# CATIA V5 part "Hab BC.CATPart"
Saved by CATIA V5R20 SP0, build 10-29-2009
Part number: Hab BC
Bounding box of the stored display mesh (mm): x -10 to 0, y -419.304 to 209.7, z -16.563 to 441.04
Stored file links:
  D:\Dropbox\IAO_2012\IAO_2012_766_vlaroche\vlaroche\vlaroche\IAO\A rendre\Hab BC.CATPart
  D:\Catia\IAO\A rendre\Assemblage.CATProduct
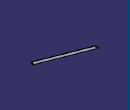
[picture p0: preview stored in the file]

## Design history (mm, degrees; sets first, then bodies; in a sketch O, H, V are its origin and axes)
Set1
  Point1: linked copy from another document
  Point2: linked copy from another document
Body1 (main body)
  Sketch1 on yz-plane, origin (0, 0, 0), H (0, 1, 0), V (0, 0, 1)
    construction line L1 (-409.3323, -6.5908) -> (199.7278, 431.0686)
    point P1 (-409.3323, -6.5908)
    point P2 (199.7278, 431.0686)
    line L2 (-415.1678, 1.53) -> (193.8923, 439.1894)
    line L3 (205.5633, 422.9478) -> (-403.4969, -14.7116)
    arc A1 centre (199.7278, 431.0686) radius 10 from (193.8923, 439.1894) to (205.5633, 422.9478) cw
    arc A2 centre (-409.3323, -6.5908) radius 10 from (-403.4969, -14.7116) to (-415.1678, 1.53) cw
    reference projected point E1 (-409.3323, -6.5908) from Point1
    reference projected point E2 (199.7278, 431.0686) from Point2
    circle A3 centre (-409.3323, -6.5908) radius 5
    circle A4 centre (199.7278, 431.0686) radius 5
    point P7 (199.7278, 431.0686)
    distance L1 L2 = 10
    radius A3 = 5
    radius A4 = 5
    tangency: A1 L2, A2 L2, A1 L3, A2 L3
    coincidence: P1 E1, P2 E2, P7 L1
  Pad1: profile Sketch1, direction (-1, 0, 0), length 10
